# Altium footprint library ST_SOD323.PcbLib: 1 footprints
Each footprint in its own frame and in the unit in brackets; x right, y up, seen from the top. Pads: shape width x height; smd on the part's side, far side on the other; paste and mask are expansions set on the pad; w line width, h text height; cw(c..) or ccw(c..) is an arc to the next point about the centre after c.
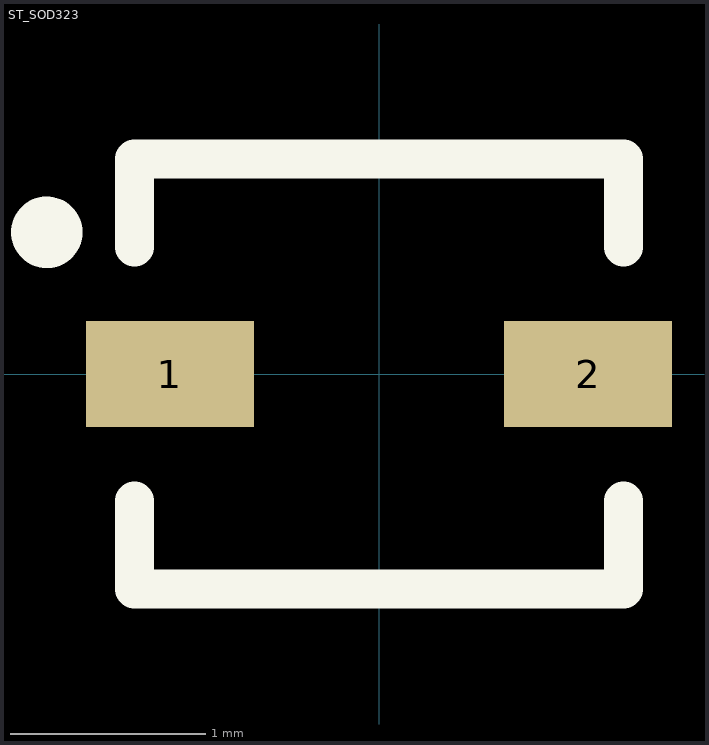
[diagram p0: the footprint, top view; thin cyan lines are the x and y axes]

## ST_SOD323 [mm]
pads (2):
  rect 0.86x0.54 smd: 1(-1.07,0) 2(1.07,0)
Top Overlay:
  circle w0.254: c-1.7,0.725 r0.056
  lines w0.2: -1.25,-0.65 -1.25,-1.1 1.25,-1.1 1.25,-0.65 ; -1.25,0.65 -1.25,1.1 1.25,1.1 1.25,0.65
3D body: height 1.17, standoff 0, extent -0.9,-0.725 0.9,0.725
3D body: height 1.17, standoff 0, extent 0.775,0.525 0.775,0.525
3D body: height 1.17, standoff 0, extent 0.9,0.75 0.9,0.75
3D body: height 1.17, standoff 0, extent -0.55,1.15 -0.55,1.15
3D body: height 1.17, standoff 0, extent -0.825,0.625 -0.825,0.625
3D body: height 1.17, standoff 0, extent 0,0 0,0
3D body: height 1.17, standoff 0, extent -0.05,-0.7 -0.05,-0.7
3D body: height 1.17, standoff 0, extent 0.9,0.75 0.9,0.75
3D body: height 1.17, standoff 0, extent 1.6,0.8 1.6,0.8
3D body: height 1.17, standoff 0, extent 0.9,0.75 0.9,0.75
3D body: height 1.17, standoff 0, extent 0.9,0.75 0.9,0.75
3D body: height 1.17, standoff 0, extent -0.05,-0.7 -0.05,-0.7
3D body: height 1.17, standoff 0, extent 0.9,0.75 0.9,0.75
3D body: height 0.25, standoff 0, extent 0.925,-0.675 0.925,-0.675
